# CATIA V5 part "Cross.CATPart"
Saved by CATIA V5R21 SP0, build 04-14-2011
Part number: 02
Material "Steel": density 7860 kg/m3, Young's modulus 2e+11 Pa, Poisson ratio 0.266, thermal expansion 1.17e-05 1/K
Bounding box of the stored display mesh (mm): x -12 to 12, y -12 to 12, z -3 to 3
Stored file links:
  G:\CATIA\Universial Joint\Cross.CATPart
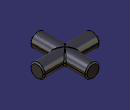
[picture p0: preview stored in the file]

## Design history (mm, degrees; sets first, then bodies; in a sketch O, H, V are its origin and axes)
Body1 (main body), material "Steel"
  Sketch1 on yz-plane, origin (0, 0, 0), H (0, 1, 0), V (0, 0, 1)
    circle A1 centre (0, 0) radius 3
    radius A1 = 3
  Pad1: profile Sketch1, direction (1, 0, 0), length 12, mirrored extent
  Sketch2 on zx-plane, origin (0, 0, 0), H (-1, 0, 0), V (0, 0, 1)
    circle A1 centre (0, 0) radius 3
    radius A1 = 3
  Pad2: profile Sketch2, direction (0, 1, 0), length 12, mirrored extent
  Fillet1: radius 0.5, on face of Pad1 from Sketch1.A1 (x2); face of Pad2 from Sketch2.A1 (x2)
